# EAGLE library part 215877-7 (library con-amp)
AMP connector
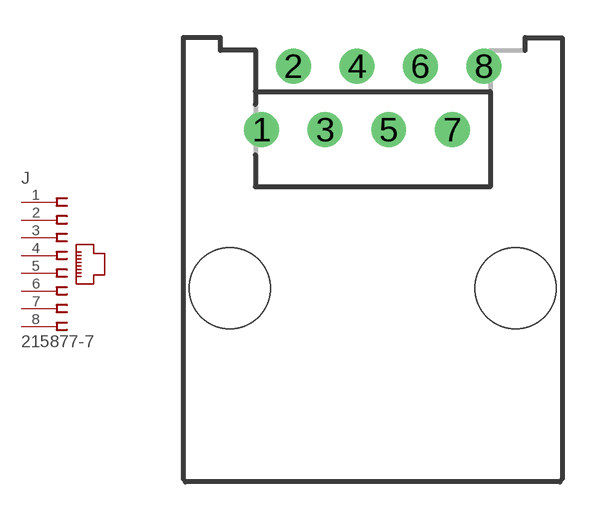
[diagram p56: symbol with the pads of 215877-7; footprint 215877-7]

Designator prefix J

## 215877-7 (OC_FARNELL: unknown; OC_NEWARK: unknown)  [215877-7]
1  1  pas
2  2  pas
3  3  pas
4  4  pas
5  5  pas
6  6  pas
7  7  pas
8  8  pas

## Footprint 215877-7 (pad centres in mm)
Modular Jack
drill 0.889 round: 1 -4.445,6.35; 2 -3.175,8.89; 3 -1.905,6.35; 4 -0.635,8.89; 5 0.635,6.35; 6 1.905,8.89; 7 3.175,6.35; 8 4.445,8.89
hole 3.251 at -5.715,0
hole 3.251 at 5.715,0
